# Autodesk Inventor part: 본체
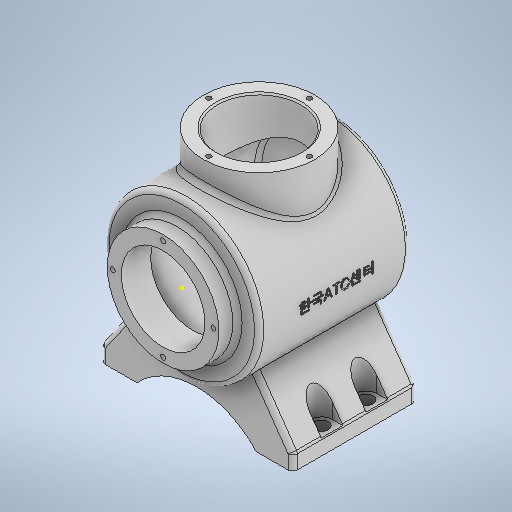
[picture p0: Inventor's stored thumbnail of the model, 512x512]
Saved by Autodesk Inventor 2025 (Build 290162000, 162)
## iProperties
Created: 2024-07
Part Number: 본체
Material: 일반
Document SubType Name: Modeling
Designer: 학생
Density: 1 g/cm^3
Appearance: 기본값
Author: 학생
## Parameters: d3 = 72 mm, d4 = 12 mm, d5 = 0, d6 = 65 mm, d26 = 226 mm, d28 = 108 mm, d29 = 90 deg, d31 = 62 mm, d32 = 72 mm, d33 = 12 mm, d34 = 0, d35 = 3 mm, d36 = -77 mm, d37 = 124 mm, d39 = 77 mm, d41 = 0, d42 = 77 mm, d43 = 124 mm, d45 = -54 mm, d46 = 55 deg, d48 = 0, d49 = 0, d50 = 0, d51 = 0, d52 = 17 mm, d55 = 0, d62 = 360 deg, d63 = 3 mm, d64 = 54 mm, d65 = 11 mm, d66 = 4 mm, d67 = 2 mm, d68 = 90 deg, d69 = 8 mm, d70 = 0, d71 = 3 mm, d72 = 1 mm, d73 = 2 mm, d74 = 45 deg, d75 = 3.242 mm, d76 = 8 mm, d77 = 4 mm, d78 = 2 mm, d79 = 90 deg, d81 = 120 deg, d82 = 65 mm, d83 = 65 mm, d84 = 3.242 mm, d85 = 8 mm, d86 = 4 mm, d87 = 2 mm, d88 = 90 deg, d90 = 120 deg, d91 = 65 mm, d92 = 65 mm, d93 = 127 mm, d94 = 62 mm, d95 = 0.5 mm, d96 = 0, d97 = 0.5 mm, d98 = 2 mm, d99 = 0, d106 = 43 mm, d107 = 19 mm, d108 = 27 mm, d110 = 7 mm, d111 = 7 mm, d112 = 7 mm, d113 = 212.12189 mm, d115 = 14 mm, d116 = 14 mm, d117 = 132 mm, d118 = 0, d119 = 3 mm, d120 = 3 mm, d121 = 14 mm, d122 = 9 mm, d123 = 6 mm, d124 = 14 mm, d125 = 2 mm, d126 = 90 deg, d127 = 6 mm, d128 = 0
